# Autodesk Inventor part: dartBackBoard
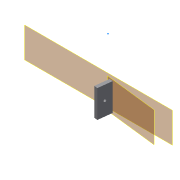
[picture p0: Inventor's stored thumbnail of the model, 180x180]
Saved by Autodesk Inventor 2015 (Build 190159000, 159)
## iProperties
Created: 2016-08
Part Number: dartBackBoard
Material: EIFS, Exterior Insulation
Document SubType Name: Modeling
Designer: user
Density: 0.023 g/cm^3
Appearance: Gray
Author: user
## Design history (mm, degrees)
workplane "Work Plane1"
workplane "Work Plane2"
sketch "Sketch2"
  geometry: L1 (25.4, 44.45)-(-25.4, 44.45); L2 (-25.4, 44.45)-(-25.4, 38.1); L3 (-25.4, 38.1)-(25.4, 38.1); L4 (25.4, 38.1)-(25.4, 44.45); 1 further point
  constraints: 8 end point, 2 parallel, 1 horizontal, 1 perpendicular
  dimensions: "d0" = 50.8 distance of L3.end L2.end; "d1" = 6.35 distance of L2.end L1.end
extrude "Extrusion1" new body sketch "Sketch2" distance "d2" = 25.4; taper "d3" = 0 deg
workplane "Work Plane3"
sketch "Sketch4"
  geometry: C1 r 2.381 at (12.7, 25.4); 1 further point
  constraints: 1 centre point
  dimensions: "d4" = 4.7625 diameter of C1
extrude "Extrusion2" cut sketch "Sketch4" distance "d5" = 25.4; taper "d6" = 0 deg
workplane "Work Plane4"
body "Solid1"
